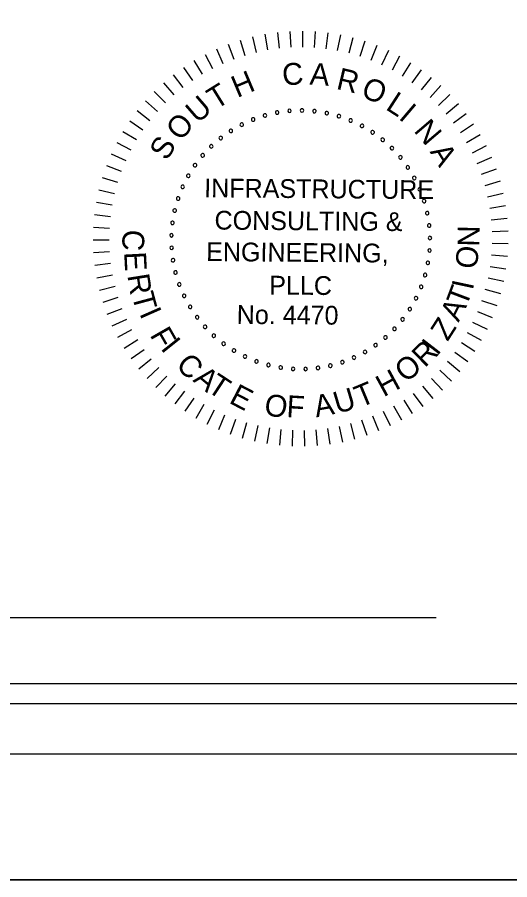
# Model space of a CAD drawing. Extents: x -1142 to 658, y -589 to 511.
# Drawn here: x 427 to 525.2, y -589.3 to -417.4 of the extents above; entities that cross this region are included whole.
import ezdxf

# ---------------------------------------------------------------- set-up
doc = ezdxf.new("R2010")
doc.units = 0
for name, color, linetype in [('BR_BORDER LINES', 7, 'Continuous'), ('BR_TEXT', 7, 'Continuous'), ('Default', 7, 'Continuous'), ('Level 31', 7, 'Continuous'), ('RD_SHT_IplotShp', 7, 'Continuous')]:
    doc.layers.add(name, color=color, linetype=linetype)

msp = doc.modelspace()

# ---------------------------------------------------------------- linework, layer by layer
at = {"layer": 'BR_BORDER LINES'}
msp.add_line((-1041.79, -564.26), (633.21, -564.26), dxfattribs=at)
at = {"layer": 'BR_TEXT'}
for p, q in [((476.32, -420.78), (476.87, -423.91)), ((478.82, -420.42), (479.18, -423.58)), ((481.33, -420.21), (481.5, -423.39)), ((483.86, -420.16), (483.83, -423.34)), ((486.38, -420.26), (486.16, -423.44)), ((488.89, -420.51), (488.48, -423.67)), ((491.38, -420.92), (490.77, -424.05)), ((469.02, -422.76), (470.13, -425.74)), ((471.41, -421.95), (472.34, -425)), ((473.85, -421.29), (474.59, -424.39)), ((493.84, -421.48), (493.05, -424.56)), ((496.26, -422.19), (495.28, -425.22)), ((466.68, -423.71), (467.98, -426.62)), ((498.64, -423.04), (497.48, -426)), ((500.96, -424.04), (499.62, -426.92)), ((462.2, -426.04), (463.84, -428.77)), ((464.41, -424.81), (465.88, -427.63)), ((503.21, -425.17), (501.7, -427.97)), ((460.08, -427.4), (461.88, -430.02)), ((505.39, -426.45), (503.71, -429.15)), ((507.49, -427.85), (505.65, -430.44)), ((458.04, -428.89), (460, -431.4)), ((509.5, -429.38), (507.5, -431.85)), ((456.1, -430.5), (458.2, -432.88)), ((511.41, -431.02), (509.27, -433.37)), ((454.25, -432.22), (456.5, -434.48)), ((513.22, -432.78), (510.94, -435)), ((452.52, -434.06), (454.9, -436.17)), ((514.92, -434.65), (512.5, -436.72)), ((450.9, -436), (453.41, -437.96)), ((516.5, -436.62), (513.96, -438.54)), ((449.41, -438.03), (452.03, -439.84)), ((448.04, -440.15), (450.76, -441.79)), ((517.96, -438.68), (515.31, -440.44)), ((519.29, -440.83), (516.54, -442.42)), ((446.8, -442.35), (449.62, -443.82)), ((520.49, -443.05), (517.64, -444.47)), ((445.7, -444.62), (448.6, -445.92)), ((444.73, -446.95), (447.71, -448.07)), ((521.54, -445.34), (518.62, -446.59)), ((522.46, -447.69), (519.46, -448.76)), ((443.92, -449.34), (446.96, -450.28)), ((523.23, -450.09), (520.18, -450.98)), ((443.25, -451.78), (446.34, -452.52)), ((523.86, -452.54), (520.75, -453.24)), ((442.73, -454.25), (445.86, -454.8)), ((524.33, -455.02), (521.19, -455.53)), ((442.36, -456.74), (445.52, -457.11)), ((524.65, -457.52), (521.48, -457.84)), ((442.14, -459.26), (445.32, -459.43)), ((524.82, -460.04), (521.64, -460.16)), ((442.08, -461.78), (445.26, -461.76)), ((524.84, -462.57), (521.65, -462.49)), ((442.17, -464.3), (445.35, -464.09)), ((524.7, -465.09), (521.52, -464.82)), ((442.42, -466.82), (445.57, -466.41)), ((524.4, -467.59), (521.25, -467.13)), ((442.81, -469.31), (445.94, -468.71)), ((443.36, -471.77), (446.45, -470.98)), ((523.96, -470.08), (520.84, -469.43)), ((523.36, -472.53), (520.29, -471.69)), ((444.06, -474.2), (447.09, -473.22)), ((522.62, -474.94), (519.61, -473.92)), ((444.91, -476.58), (447.87, -475.42)), ((521.73, -477.31), (518.78, -476.1)), ((445.89, -478.9), (448.78, -477.56)), ((447.02, -481.16), (449.82, -479.65)), ((520.7, -479.61), (517.83, -478.22)), ((519.53, -481.85), (516.75, -480.29)), ((448.29, -483.34), (450.99, -481.66)), ((518.22, -484.01), (515.55, -482.28)), ((449.68, -485.45), (452.28, -483.61)), ((516.79, -486.08), (514.22, -484.2)), ((451.2, -487.46), (453.68, -485.47)), ((515.23, -488.07), (512.78, -486.03)), ((452.84, -489.38), (455.19, -487.24)), ((513.55, -489.96), (511.24, -487.77)), ((454.59, -491.2), (456.81, -488.91)), ((511.76, -491.74), (509.59, -489.42)), ((456.46, -492.9), (458.53, -490.49)), ((509.87, -493.41), (507.84, -490.96)), ((458.42, -494.49), (460.34, -491.95)), ((460.47, -495.95), (462.24, -493.31)), ((507.88, -494.96), (506, -492.39)), ((462.61, -497.29), (464.21, -494.54)), ((503.63, -497.68), (502.08, -494.9)), ((505.8, -496.38), (504.08, -493.71)), ((464.83, -498.5), (466.26, -495.65)), ((467.12, -499.56), (468.37, -496.64)), ((501.39, -498.84), (500.01, -495.98)), ((469.47, -500.49), (470.54, -497.49)), ((471.87, -501.27), (472.76, -498.21)), ((494.3, -501.48), (493.47, -498.41)), ((496.72, -500.75), (495.69, -497.73)), ((499.08, -499.87), (497.88, -496.92)), ((474.31, -501.9), (475.01, -498.8)), ((476.79, -502.39), (477.3, -499.24)), ((479.29, -502.72), (479.61, -499.55)), ((481.81, -502.9), (481.93, -499.71)), ((484.33, -502.92), (484.26, -499.74)), ((486.85, -502.79), (486.59, -499.62)), ((489.36, -502.51), (488.9, -499.36)), ((491.85, -502.07), (491.2, -498.95))]:
    msp.add_line(p, q, dxfattribs=at)
for centre, start, end in [((476.35, -436.97), 16.1422, 196.1422), ((478.78, -436.4), 10.6038, 190.6038), ((478.78, -436.4), 190.6038, 10.6038), ((481.24, -436.06), 5.0653, 185.0653), ((481.24, -436.06), 185.0653, 5.0653), ((483.73, -435.97), 359.5268, 179.5268), ((483.73, -435.97), 179.5268, 359.5268), ((486.22, -436.11), 353.9884, 173.9884), ((486.22, -436.11), 173.9884, 353.9884), ((488.68, -436.5), 168.4499, 348.4499), ((488.68, -436.5), 348.4499, 168.4499), ((473.99, -437.77), 21.6807, 201.6807), ((473.99, -437.77), 201.6807, 21.6807), ((476.35, -436.97), 196.1422, 16.1422), ((491.1, -437.12), 162.9114, 342.9114), ((491.1, -437.12), 342.9114, 162.9114), ((493.44, -437.97), 157.373, 337.373), ((493.44, -437.97), 337.373, 157.373), ((469.56, -440.04), 32.7576, 212.7576), ((469.56, -440.04), 212.7576, 32.7576), ((471.72, -438.8), 27.2191, 207.2191), ((471.72, -438.8), 207.2191, 27.2191), ((495.69, -439.04), 151.8345, 331.8345), ((495.69, -439.04), 331.8345, 151.8345), ((497.82, -440.33), 146.2961, 326.2961), ((497.82, -440.33), 326.2961, 146.2961), ((467.53, -441.48), 38.2961, 218.2961), ((467.53, -441.48), 218.2961, 38.2961), ((499.82, -441.81), 140.7576, 320.7576), ((499.82, -441.81), 320.7576, 140.7576), ((465.65, -443.12), 43.8345, 223.8345), ((465.65, -443.12), 223.8345, 43.8345), ((501.67, -443.48), 135.2191, 315.2191), ((501.67, -443.48), 315.2191, 135.2191), ((463.93, -444.92), 49.373, 229.373), ((463.93, -444.92), 229.373, 49.373), ((503.35, -445.33), 129.6807, 309.6807), ((503.35, -445.33), 309.6807, 129.6807), ((462.4, -446.89), 54.9114, 234.9114), ((462.4, -446.89), 234.9114, 54.9114), ((504.84, -447.32), 304.1422, 124.1422), ((461.06, -448.99), 60.4499, 240.4499), ((461.06, -448.99), 240.4499, 60.4499), ((504.84, -447.32), 124.1422, 304.1422), ((506.13, -449.45), 118.6038, 298.6038), ((506.13, -449.45), 298.6038, 118.6038), ((459.94, -451.21), 65.9884, 245.9884), ((459.94, -451.21), 245.9884, 65.9884), ((507.21, -451.7), 113.0653, 293.0653), ((507.21, -451.7), 293.0653, 113.0653), ((459.03, -453.53), 71.5268, 251.5268), ((459.03, -453.53), 251.5268, 71.5268), ((508.07, -454.03), 107.5268, 287.5268), ((508.07, -454.03), 287.5268, 107.5268), ((458.35, -455.93), 77.0653, 257.0653), ((458.35, -455.93), 257.0653, 77.0653), ((508.7, -456.44), 101.9884, 281.9884), ((508.7, -456.44), 281.9884, 101.9884), ((457.91, -458.38), 82.6038, 262.6038), ((457.91, -458.38), 262.6038, 82.6038), ((509.1, -458.91), 96.4499, 276.4499), ((509.1, -458.91), 276.4499, 96.4499), ((457.7, -460.86), 88.1422, 268.1422), ((457.7, -460.86), 268.1422, 88.1422), ((509.25, -461.39), 90.9114, 270.9114), ((509.25, -461.39), 270.9114, 90.9114), ((457.73, -463.36), 93.6807, 273.6807), ((457.73, -463.36), 273.6807, 93.6807), ((509.17, -463.88), 85.373, 265.373), ((509.17, -463.88), 265.373, 85.373), ((458.01, -465.83), 99.2191, 279.2191), ((458.01, -465.83), 279.2191, 99.2191), ((508.84, -466.35), 79.8345, 259.8345), ((508.84, -466.35), 259.8345, 79.8345), ((458.52, -468.27), 104.7576, 284.7576), ((458.52, -468.27), 284.7576, 104.7576), ((508.28, -468.78), 74.2961, 254.2961), ((508.28, -468.78), 254.2961, 74.2961), ((459.27, -470.65), 110.2961, 290.2961), ((459.27, -470.65), 290.2961, 110.2961), ((507.48, -471.14), 68.7576, 248.7576), ((507.48, -471.14), 248.7576, 68.7576), ((460.24, -472.94), 115.8345, 295.8345), ((460.24, -472.94), 295.8345, 115.8345), ((506.47, -473.41), 63.2191, 243.2191), ((506.47, -473.41), 243.2191, 63.2191), ((461.43, -475.13), 121.373, 301.373), ((461.43, -475.13), 301.373, 121.373), ((505.23, -475.58), 57.6807, 237.6807), ((505.23, -475.58), 237.6807, 57.6807), ((462.82, -477.2), 126.9114, 306.9114), ((462.82, -477.2), 306.9114, 126.9114), ((503.8, -477.62), 52.1422, 232.1422), ((503.8, -477.62), 232.1422, 52.1422), ((464.41, -479.12), 132.4499, 312.4499), ((464.41, -479.12), 312.4499, 132.4499), ((502.17, -479.5), 46.6038, 226.6038), ((502.17, -479.5), 226.6038, 46.6038), ((466.17, -480.88), 137.9884, 317.9884), ((466.17, -480.88), 317.9884, 137.9884), ((500.37, -481.23), 41.0653, 221.0653), ((500.37, -481.23), 221.0653, 41.0653), ((468.1, -482.46), 143.5268, 323.5268), ((468.1, -482.46), 323.5268, 143.5268), ((498.41, -482.77), 35.5268, 215.5268), ((498.41, -482.77), 215.5268, 35.5268), ((470.17, -483.84), 149.0653, 329.0653), ((470.17, -483.84), 329.0653, 149.0653), ((472.37, -485.02), 334.6038, 154.6038), ((496.31, -484.11), 29.9884, 209.9884), ((496.31, -484.11), 209.9884, 29.9884), ((472.37, -485.02), 154.6038, 334.6038), ((474.66, -485.99), 160.1422, 340.1422), ((474.66, -485.99), 340.1422, 160.1422), ((477.04, -486.72), 345.6807, 165.6807), ((489.38, -486.85), 13.373, 193.373), ((491.78, -486.16), 18.9114, 198.9114), ((491.78, -486.16), 198.9114, 18.9114), ((494.1, -485.24), 24.4499, 204.4499), ((494.1, -485.24), 204.4499, 24.4499), ((477.04, -486.72), 165.6807, 345.6807), ((479.48, -487.23), 171.2191, 351.2191), ((479.48, -487.23), 351.2191, 171.2191), ((481.96, -487.49), 356.7576, 176.7576), ((481.96, -487.49), 176.7576, 356.7576), ((484.45, -487.52), 2.2961, 182.2961), ((484.45, -487.52), 182.2961, 2.2961), ((486.93, -487.3), 7.8345, 187.8345), ((486.93, -487.3), 187.8345, 7.8345), ((489.38, -486.85), 193.373, 13.373)]:
    msp.add_arc(centre, 0.351, start, end, dxfattribs=at)
at = {"layer": 'Default'}
msp.add_line((371.83, -537.07), (510.46, -537.07), dxfattribs=at)
for points in [[(275.07, -376.26), (593.07, -376.26), (593.07, -554.26), (275.07, -554.26)], [(279.07, -380.26), (589.07, -380.26), (589.07, -550.26), (279.07, -550.26)]]:
    msp.add_lwpolyline(points, close=True, dxfattribs=at)
at = {"layer": 'Level 31'}
msp.add_lwpolyline([(-1141.79, 510.67), (-1141.79, -589.33), (658.21, -589.33), (658.21, 510.67)], dxfattribs=at)
at = {"layer": 'RD_SHT_IplotShp'}
msp.add_line((-1141.79, -589.26), (658.21, -589.26), dxfattribs=at)

# ---------------------------------------------------------------- texts
at = {"layer": 'BR_TEXT'}
for s, height, rotation, p in [('C', 4.36, 4.7281, (479.96, -431.04)), ('H', 4.36, 22.7882, (470.82, -433.51)), ('A', 4.36, 355.6981, (485.18, -430.79)), ('R', 4.36, 346.6681, (490.4, -431.64)), ('O', 4.36, 337.638, (495.28, -433.13)), ('T', 4.36, 31.8182, (466.57, -435.89)), ('U', 4.36, 40.8482, (462.91, -438.7)), ('L', 4.36, 327.108, (500.23, -435.65)), ('I', 4.36, 319.578, (502.85, -437.54)), ('O', 4.36, 49.8782, (459.56, -442.25)), ('N', 4.36, 310.548, (505.89, -440.08)), ('S', 4.36, 58.9083, (456.79, -446.16)), ('A', 4.36, 301.5179, (509.15, -444.2)), ('INFRASTRUCTURE', 3.7386, 359.5268, (464.22, -453.28)), ('CONSULTING &', 3.7386, 359.5268, (466.28, -459.71)), ('C', 4.36, 267.025, (448.04, -459.65)), ('N', 4.36, 89.2085, (519.11, -463.14)), ('ENGINEERING,', 3.7386, 359.5268, (464.61, -465.99)), ('O', 4.36, 83.2085, (518.56, -467.71)), ('E', 4.36, 273.025, (448.26, -464.23)), ('R', 4.36, 279.025, (448.9, -468.85)), ('PLLC', 3.739, 359.5268, (477.19, -472.66)), ('T', 4.36, 69.3954, (516.5, -475.3)), ('I', 4.36, 77.9093, (517.78, -471.93)), ('T', 4.36, 285.025, (449.77, -472.79)), ('A', 4.36, 63.3954, (514.96, -478.32)), ('I', 4.36, 293.7713, (451.25, -476.44)), ('No. 4470', 3.739, 359.5268, (470.71, -478.51)), ('Z', 4.36, 57.3954, (512.77, -482.14)), ('F', 4.36, 299.7713, (453.31, -480.74)), ('I', 4.36, 308.5268, (455.42, -483.44)), ('R', 4.36, 44.5268, (508.24, -487.39)), ('I', 4.36, 52.3339, (510.71, -485.02)), ('C', 4.36, 314.5268, (458.39, -486.94)), ('O', 4.36, 38.5268, (504.41, -490.38)), ('A', 4.36, 320.5268, (461.84, -489.87)), ('T', 4.36, 326.5268, (464.57, -491.8)), ('H', 4.36, 28.5268, (500.01, -493.18)), ('T', 4.36, 22.5268, (495.35, -495.27)), ('E', 4.36, 332.5268, (468.99, -494.18)), ('U', 4.36, 16.5268, (490.76, -496.49)), ('O', 4.36, 350.5268, (476, -496.63)), ('F', 4.36, 356.5268, (480.57, -497.08)), ('A', 4.36, 10.5268, (486.57, -497.17))]:
    msp.add_text(s, height=height, rotation=rotation, dxfattribs=at).set_placement(p)

doc.saveas('drawing.dxf')
